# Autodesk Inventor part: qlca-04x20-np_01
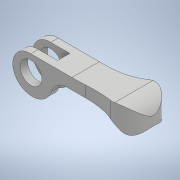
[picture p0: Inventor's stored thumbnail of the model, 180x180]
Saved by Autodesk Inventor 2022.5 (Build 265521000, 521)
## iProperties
Part Number: qlca-04x20-np_01
Material: 一般
Document SubType Name: Modeling
Designer: ImaoCorp
Density: 1 g/cm^3
Appearance: 既定
Author: ImaoCorp
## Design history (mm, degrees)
feature "qlca-04x20-np_01"
node "ソリッド1"
